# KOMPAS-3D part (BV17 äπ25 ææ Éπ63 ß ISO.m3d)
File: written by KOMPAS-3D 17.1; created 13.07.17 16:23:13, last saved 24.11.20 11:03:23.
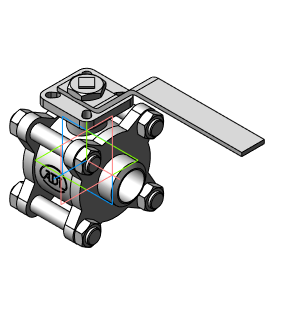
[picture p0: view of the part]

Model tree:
1. Операция без истории:1  (labels: Сталь 20  ГОСТ 1050-88)

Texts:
  DISO1
  DISO2
  BV17 Ду8 1/4" Ру63 с ISO
  BV17 Ду8 СС Ру63 с ISO
  BV17 Ду10 3/8" Ру63 с ISO
  BV17 Ду10 СС Ру63 с ISO
  BV17 Ду15 1/2" Ру63 с ISO
  BV17 Ду15 СС Ру63 с ISO
  BV17 Ду15 ФФ Ру40 с ISO
  BV17 Ду20 3/4" Ру63 с ISO
  BV17 Ду20 СС Ру40 с ISO
  BV17 Ду20 ФФ Ру40 с ISO
  BV17 Ду25 1" Ру63 с ISO
  BV17 Ду25 СС Ру63 с ISO
  BV17 Ду25 ФФ Ру40 с ISO
  BV17 Ду32 1 1/4" Ру63 с ISO
  BV17 Ду32 СС Ру63 с ISO
  BV17 Ду32 ФФ Ру40 с ISO
  BV17 Ду40 1 1/2" Ру63 с ISO
  BV17 Ду40 СС Ру63 с ISO
  BV17 Ду40 ФФ Ру40 с ISO
  BV17 Ду50 2" Ру63 с ISO
  BV17 Ду50 СС Ру63 с ISO
  BV17 Ду50 ФФ Ру40 с ISO
  BV17 Ду65 2 1/2" Ру40 с ISO
  BV17 Ду65 СС Ру40 с ISO
  BV17 Ду65 ФФ Ру40 с ISO
  BV17 Ду80 3" Ру40 с ISO
  BV17 Ду80 СС Ру40 с ISO
  BV17 Ду80 ФФ Ру40 с ISO
  BV17 Ду100 4" Ру40 с ISO
  BV17 Ду100 СС Ру40 с ISO
  BV17 Ду100 ФФ Ру40 с ISO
